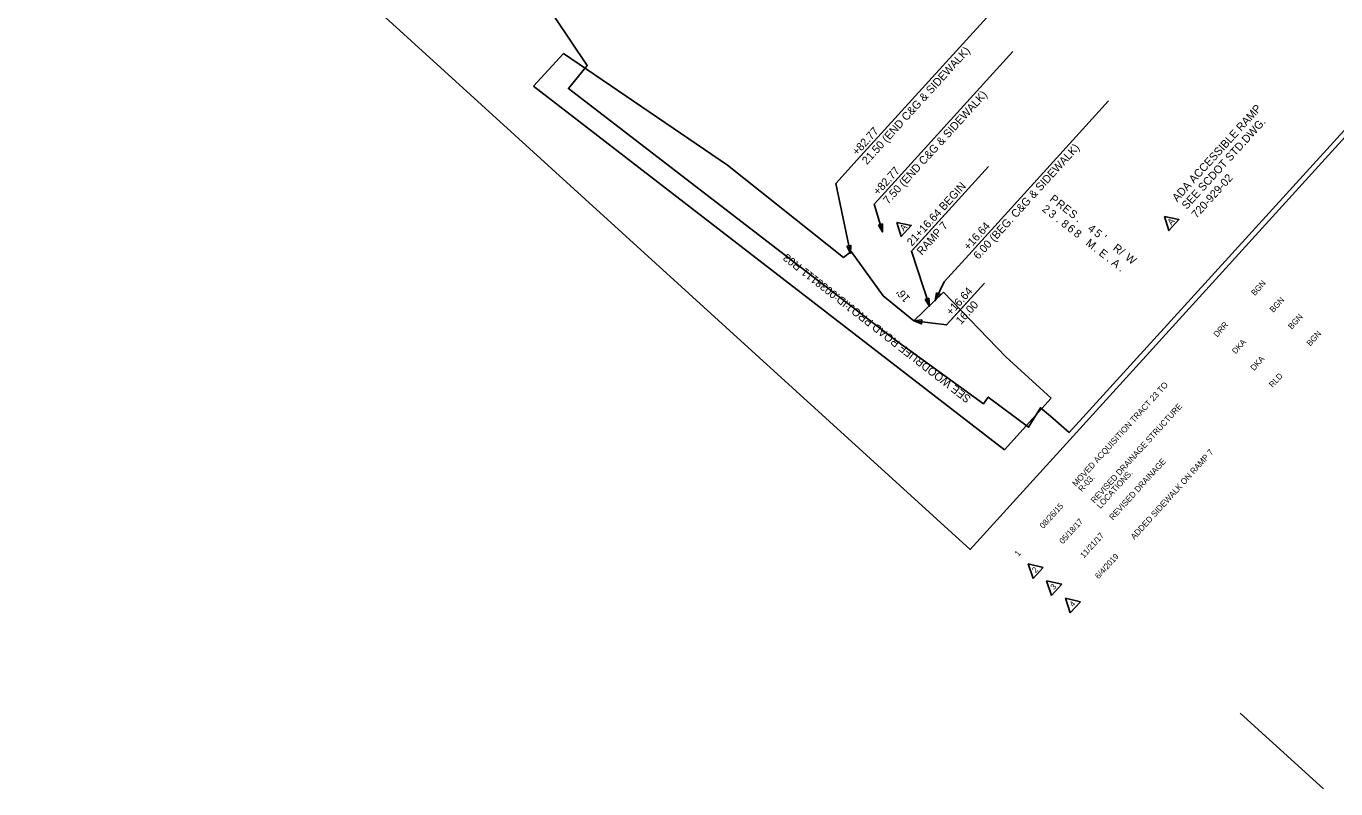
# Model space of a CAD drawing. Extents: x 1608705 to 1610581, y 1091647 to 1093887.
# Drawn here: x 1608729 to 1609711, y 1091823 to 1092394 of the extents above; entities that cross this region are included whole.
import ezdxf

# ---------------------------------------------------------------- set-up
doc = ezdxf.new("R2010")
doc.units = 0
for name, color, linetype in [('Default', 7, 'Continuous'), ('Level 2', 7, 'Continuous'), ('Plan_Clip', 7, 'Continuous'), ('RD_EX_RW_TX', 7, 'Continuous'), ('RD_SHT_TX', 7, 'Continuous')]:
    doc.layers.add(name, color=color, linetype=linetype)

msp = doc.modelspace()

# ---------------------------------------------------------------- linework, layer by layer
at = {"layer": 'Default'}
for p, q in [((1609131.99, 1092373.29), (1609109.38, 1092348.75)), ((1609254.77, 1092289.73), (1609131.99, 1092373.29)), ((1609109.38, 1092348.75), (1609462.5, 1092076.5)), ((1609341.87, 1092220.54), (1609254.77, 1092289.73)), ((1609347.57, 1092224.87), (1609341.87, 1092220.54)), ((1609371.41, 1092191.73), (1609347.57, 1092224.87)), ((1609416.83, 1092194.64), (1609394.48, 1092173.08)), ((1609463.59, 1092146.19), (1609416.83, 1092194.64)), ((1609394.48, 1092173.08), (1609371.41, 1092191.73)), ((1609497.56, 1092115.04), (1609463.59, 1092146.19)), ((1609462.5, 1092076.5), (1609497.56, 1092115.04))]:
    msp.add_line(p, q, dxfattribs=at)
at = {"layer": 'Level 2'}
msp.add_lwpolyline([(1608729.11, 1092645.4), (1609856.11, 1093884.55), (1610563.72, 1093240.99), (1609436.73, 1092001.83)], close=True, dxfattribs=at)
at = {"layer": 'Plan_Clip'}
msp.add_lwpolyline([(1610402.66, 1093068.39), (1609510.9, 1092089.32), (1609496.88, 1092101.66), (1609489.45, 1092107.95), (1609480.57, 1092093.35), (1609450.27, 1092115.95), (1609446.7, 1092110.96), (1609379.78, 1092159.35), (1609135.57, 1092347.04), (1609149.57, 1092364.39), (1609089.98, 1092453.43)], dxfattribs=at)
msp.add_lwpolyline([(1610402.66, 1093068.39), (1609510.9, 1092089.32), (1609496.88, 1092101.66), (1609489.45, 1092107.95), (1609480.57, 1092093.35), (1609450.27, 1092115.95), (1609446.7, 1092110.96), (1609379.78, 1092159.35), (1609135.57, 1092347.04), (1609149.57, 1092364.39), (1609089.98, 1092453.43)], dxfattribs=at)
at = {"layer": 'RD_SHT_TX'}
for p, q in [((1609456.95, 1092408.82), (1609352.12, 1092293.56)), ((1609468.79, 1092374.75), (1609367.97, 1092263.89)), ((1609540.47, 1092337.8), (1609435.64, 1092222.54)), ((1609450.48, 1092288.77), (1609393.18, 1092225.76)), ((1609447.6, 1092201.31), (1609422.53, 1092173.75)), ((1609491.53, 1091988.38), (1609480.19, 1091991)), ((1609480.19, 1091991), (1609483.86, 1091979.96)), ((1609483.86, 1091979.96), (1609491.53, 1091988.38)), ((1609505.36, 1091975.8), (1609494.02, 1091978.42)), ((1609494.02, 1091978.42), (1609497.7, 1091967.38)), ((1609497.7, 1091967.38), (1609505.36, 1091975.8)), ((1609519.44, 1091962.69), (1609508.1, 1091965.3)), ((1609508.1, 1091965.3), (1609511.78, 1091954.26)), ((1609511.78, 1091954.26), (1609519.44, 1091962.69)), ((1609701.48, 1091822.59), (1609639.22, 1091879.21))]:
    msp.add_line(p, q, dxfattribs=at)
for points in [[(1609352.12, 1092293.56), (1609336.07, 1092275.91), (1609346.96, 1092223.61)], [(1609450.48, 1092288.77), (1609392.75, 1092225.28), (1609406.16, 1092184.02)], [(1609367.97, 1092263.89), (1609364.87, 1092260.48), (1609371.08, 1092239.72)], [(1609435.64, 1092222.54), (1609417.3, 1092202.37), (1609410.5, 1092188.17)], [(1609447.6, 1092201.31), (1609419.08, 1092169.95), (1609394.59, 1092172.96)]]:
    msp.add_lwpolyline(points, dxfattribs=at)
for points in [[(1609367.93, 1092244.82), (1609371.08, 1092239.72), (1609370.91, 1092245.71)], [(1609381.7, 1092246.83), (1609385.07, 1092236.28), (1609392.51, 1092244.47)], [(1609582.34, 1092251.24), (1609585.71, 1092240.69), (1609593.16, 1092248.88)], [(1609344.26, 1092228.97), (1609346.96, 1092223.61), (1609347.3, 1092229.6)], [(1609411.6, 1092194.06), (1609410.5, 1092188.17), (1609414.4, 1092192.72)], [(1609402.89, 1092189.05), (1609406.16, 1092184.02), (1609405.84, 1092190.01)], [(1609400.54, 1092173.8), (1609394.59, 1092172.96), (1609400.16, 1092170.71)]]:
    msp.add_lwpolyline(points, close=True, dxfattribs=at)

# ---------------------------------------------------------------- texts
at = {"layer": 'RD_EX_RW_TX'}
for s, p in [('P', (1609495.84, 1092263.39)), ('R', (1609500.58, 1092259.71)), ('2', (1609490.12, 1092255.8)), ('3', (1609494.86, 1092252.12)), ('E', (1609505.34, 1092256.01)), ('S', (1609510.05, 1092252.34)), ('.', (1609500.57, 1092247.68)), ('8', (1609504.34, 1092244.75)), ('6', (1609508.96, 1092241.16)), ('.', (1609515.87, 1092247.82)), ('4', (1609524.38, 1092241.21)), ('5', (1609529.12, 1092237.53)), ('8', (1609513.81, 1092237.39)), ('M', (1609522.88, 1092230.35)), ("'", (1609534.83, 1092233.1)), ('.', (1609529, 1092225.59)), ('E', (1609532.67, 1092222.74)), ('R', (1609543.22, 1092226.57)), ('/', (1609547.88, 1092222.95)), ('W', (1609552.4, 1092219.44)), ('.', (1609538.47, 1092218.23)), ('A', (1609542.06, 1092215.45)), ('.', (1609547.95, 1092210.87))]:
    msp.add_text(s, height=6, rotation=322.15475, dxfattribs=at).set_placement(p)
at = {"layer": 'RD_SHT_TX'}
for s, height, rotation, p in [('21.50 (END C&G & SIDEWALK)', 6, 47.71377, (1609359.39, 1092289.66)), ('7.50 (END C&G & SIDEWALK)', 6, 47.71377, (1609375.23, 1092259.99)), ('ADA ACCESSIBLE RAMP', 6, 47.71377, (1609591.92, 1092261.82)), ('SEE SCDOT STD.DWG.', 6, 47.71377, (1609599.05, 1092256.13)), ('+82.77', 6, 47.71377, (1609351.99, 1092296.39)), ('6.00 (BEG. C&G & SIDEWALK)', 6, 47.71377, (1609442.91, 1092218.64)), ('+82.77', 6, 47.71377, (1609367.83, 1092266.72)), ('720-929-02', 6, 47.71377, (1609606.45, 1092249.4)), ('21+16.64 BEGIN', 6, 47.71377, (1609393.05, 1092228.59)), ('A', 4.8, 47.71377, (1609386.97, 1092239.86)), ('RAMP 7', 6, 47.71377, (1609400.45, 1092221.86)), ('+16.64', 6, 47.71377, (1609435.51, 1092225.37)), ('A', 4.8, 47.71377, (1609587.61, 1092244.27)), ('SEE WOODRUFF ROAD PROJ:ID:0038111-R03', 6, 142.01025, (1609437.9, 1092115.71)), ('BGN', 4.4, 47.71377, (1609650.17, 1092191.56)), ("16'", 6, 130.44184, (1609392.18, 1092189.89)), ('+16.64', 6, 47.71377, (1609422.4, 1092176.57)), ('16.00', 6, 47.71377, (1609429.8, 1092169.84)), ('BGN', 4.4, 47.7154, (1609664, 1092178.97)), ('BGN', 4.4, 47.7154, (1609677.83, 1092166.39)), ('DRR', 4.4, 47.71377, (1609621.91, 1092160.48)), ('BGN', 4.4, 47.71377, (1609691.67, 1092153.81)), ('DKA', 4.4, 47.7154, (1609635.76, 1092147.93)), ('DKA', 4.4, 47.7154, (1609649.6, 1092135.35)), ('MOVED ACQUISITION TRACT 23 TO ', 4.5, 47.7154, (1609516.14, 1092048.62)), ('RLD', 4.4, 47.71377, (1609663.48, 1092122.82)), ('REVISED DRAINAGE STRUCTURE', 4.5, 47.7154, (1609529.97, 1092036.04)), ('ADDED SIDEWALK ON RAMP 7', 4.5, 47.71377, (1609559.88, 1092008.83)), ('REVISED DRAINAGE ', 4.5, 47.7154, (1609543.8, 1092023.46)), ('R-03.', 4.5, 47.7154, (1609520.57, 1092044.59)), ('LOCATIONS.', 4.5, 47.7154, (1609534.4, 1092032.01)), ('08/26/15', 4.4, 47.71377, (1609491.55, 1092017.16)), ('05/18/17', 4.4, 47.7154, (1609506.31, 1092005.6)), ('11/21/17', 4.4, 47.7154, (1609521.98, 1091995.03)), ('1', 4.4, 47.71377, (1609472.88, 1091996.21)), ('6/4/2019', 4.4, 47.71377, (1609533.05, 1091979.41)), ('2', 4.4, 47.7154, (1609485.81, 1091983.85)), ('3', 4.4, 47.7154, (1609499.64, 1091971.27)), ('4', 4.4, 47.71377, (1609513.88, 1091958.33))]:
    msp.add_text(s, height=height, rotation=rotation, dxfattribs=at).set_placement(p)

doc.saveas('drawing.dxf')
